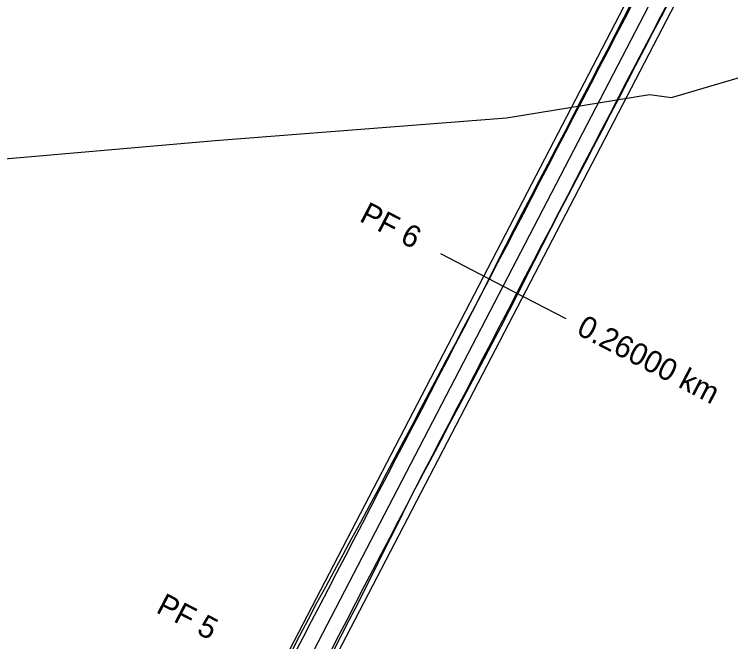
# Model space of a CAD drawing. Extents: x -555887 to -552101, y -1100251 to -1096546.
# Drawn here: x -553807.8 to -553726.6, y -1097465.4 to -1097394.3 of the extents above; entities that cross this region are included whole.
import ezdxf

# ---------------------------------------------------------------- set-up
doc = ezdxf.new("R2010")
doc.units = 0
for name, color, linetype in [('PARCELY_cesty', 7, 'Continuous'), ('POLYGONY_SITUACE_PF', 7, 'Continuous'), ('POLYGONY_SITUACE_PF_POPISY', 7, 'Continuous'), ('POLYGONY_SITUACE_PO', 7, 'Continuous'), ('vrstevnice', 7, 'Continuous')]:
    doc.layers.add(name, color=color, linetype=linetype)

msp = doc.modelspace()

# ---------------------------------------------------------------- linework, layer by layer
at = {"layer": 'PARCELY_cesty'}
for points in [[(-553665.731, -1097263.939), (-553869.18, -1097655.12), (-553873.9, -1097664.18), (-553876.67, -1097669.5)], [(-553672.865, -1097266.819), (-553859.38, -1097625.46)]]:
    msp.add_lwpolyline(points, dxfattribs=at)
at = {"layer": 'POLYGONY_SITUACE_PF'}
for p, q in [((-553759.461, -1097421.407), (-553752.363, -1097425.098)), ((-553752.363, -1097425.098), (-553745.266, -1097428.789))]:
    msp.add_line(p, q, dxfattribs=at)
at = {"layer": 'POLYGONY_SITUACE_PO'}
for p, q in [((-553872.328, -1097655.768), (-553671.456, -1097269.528)), ((-553734.469, -1097394.484), (-553733.508, -1097392.636)), ((-553734.469, -1097394.484), (-553733.508, -1097392.636)), ((-553734.417, -1097394.512), (-553733.459, -1097392.661)), ((-553737.709, -1097392.799), (-553738.667, -1097394.65)), ((-553738.536, -1097394.718), (-553737.575, -1097392.869)), ((-553738.536, -1097394.718), (-553737.575, -1097392.869)), ((-553738.667, -1097394.65), (-553739.624, -1097396.5)), ((-553739.497, -1097396.566), (-553738.536, -1097394.718)), ((-553739.497, -1097396.566), (-553738.536, -1097394.718)), ((-553735.431, -1097396.333), (-553734.469, -1097394.484)), ((-553735.431, -1097396.333), (-553734.469, -1097394.484)), ((-553735.374, -1097396.362), (-553734.417, -1097394.512)), ((-553739.624, -1097396.5), (-553740.581, -1097398.35)), ((-553740.458, -1097398.414), (-553739.497, -1097396.566)), ((-553740.458, -1097398.414), (-553739.497, -1097396.566)), ((-553736.392, -1097398.181), (-553735.431, -1097396.333)), ((-553736.392, -1097398.181), (-553735.431, -1097396.333)), ((-553736.333, -1097398.211), (-553735.374, -1097396.362)), ((-553740.581, -1097398.35), (-553741.539, -1097400.201)), ((-553741.42, -1097400.263), (-553740.458, -1097398.414)), ((-553741.42, -1097400.263), (-553740.458, -1097398.414)), ((-553737.353, -1097400.029), (-553736.392, -1097398.181)), ((-553737.353, -1097400.029), (-553736.392, -1097398.181)), ((-553737.296, -1097400.059), (-553736.333, -1097398.211)), ((-553738.314, -1097401.878), (-553737.353, -1097400.029)), ((-553738.314, -1097401.878), (-553737.353, -1097400.029)), ((-553738.258, -1097401.907), (-553737.296, -1097400.059)), ((-553741.539, -1097400.201), (-553742.496, -1097402.051)), ((-553742.381, -1097402.111), (-553741.42, -1097400.263)), ((-553742.381, -1097402.111), (-553741.42, -1097400.263)), ((-553742.496, -1097402.051), (-553743.457, -1097403.9)), ((-553743.342, -1097403.959), (-553742.381, -1097402.111)), ((-553743.342, -1097403.959), (-553742.381, -1097402.111)), ((-553739.276, -1097403.726), (-553738.314, -1097401.878)), ((-553739.276, -1097403.726), (-553738.314, -1097401.878)), ((-553739.22, -1097403.755), (-553738.258, -1097401.907)), ((-553743.457, -1097403.9), (-553744.419, -1097405.748)), ((-553744.303, -1097405.808), (-553743.342, -1097403.959)), ((-553744.303, -1097405.808), (-553743.342, -1097403.959)), ((-553740.237, -1097405.574), (-553739.276, -1097403.726)), ((-553740.237, -1097405.574), (-553739.276, -1097403.726)), ((-553740.182, -1097405.603), (-553739.22, -1097403.755)), ((-553744.419, -1097405.748), (-553745.381, -1097407.596)), ((-553741.198, -1097407.422), (-553740.237, -1097405.574)), ((-553741.198, -1097407.422), (-553740.237, -1097405.574)), ((-553741.144, -1097407.451), (-553740.182, -1097405.603)), ((-553745.265, -1097407.656), (-553744.303, -1097405.808)), ((-553745.265, -1097407.656), (-553744.303, -1097405.808)), ((-553745.381, -1097407.596), (-553746.343, -1097409.443)), ((-553746.226, -1097409.504), (-553745.265, -1097407.656)), ((-553746.226, -1097409.504), (-553745.265, -1097407.656)), ((-553742.159, -1097409.271), (-553741.198, -1097407.422)), ((-553742.159, -1097409.271), (-553741.198, -1097407.422)), ((-553742.106, -1097409.299), (-553741.144, -1097407.451)), ((-553746.343, -1097409.443), (-553747.305, -1097411.291)), ((-553747.187, -1097411.353), (-553746.226, -1097409.504)), ((-553747.187, -1097411.353), (-553746.226, -1097409.504)), ((-553743.121, -1097411.119), (-553742.159, -1097409.271)), ((-553743.121, -1097411.119), (-553742.159, -1097409.271)), ((-553743.068, -1097411.147), (-553742.106, -1097409.299)), ((-553747.305, -1097411.291), (-553748.267, -1097413.139)), ((-553748.148, -1097413.201), (-553747.187, -1097411.353)), ((-553748.148, -1097413.201), (-553747.187, -1097411.353)), ((-553744.082, -1097412.967), (-553743.121, -1097411.119)), ((-553744.082, -1097412.967), (-553743.121, -1097411.119)), ((-553744.03, -1097412.995), (-553743.068, -1097411.147)), ((-553745.043, -1097414.816), (-553744.082, -1097412.967)), ((-553745.043, -1097414.816), (-553744.082, -1097412.967)), ((-553744.992, -1097414.842), (-553744.03, -1097412.995)), ((-553748.267, -1097413.139), (-553749.229, -1097414.987)), ((-553749.11, -1097415.049), (-553748.148, -1097413.201)), ((-553749.11, -1097415.049), (-553748.148, -1097413.201)), ((-553749.229, -1097414.987), (-553750.191, -1097416.835)), ((-553750.071, -1097416.897), (-553749.11, -1097415.049)), ((-553750.071, -1097416.897), (-553749.11, -1097415.049)), ((-553746.004, -1097416.664), (-553745.043, -1097414.816)), ((-553746.004, -1097416.664), (-553745.043, -1097414.816)), ((-553745.954, -1097416.69), (-553744.992, -1097414.842)), ((-553750.191, -1097416.835), (-553751.149, -1097418.685)), ((-553751.032, -1097418.746), (-553750.071, -1097416.897)), ((-553751.032, -1097418.746), (-553750.071, -1097416.897)), ((-553746.966, -1097418.512), (-553746.004, -1097416.664)), ((-553746.966, -1097418.512), (-553746.004, -1097416.664)), ((-553746.916, -1097418.538), (-553745.954, -1097416.69)), ((-553751.149, -1097418.685), (-553752.09, -1097420.544)), ((-553751.993, -1097420.594), (-553751.032, -1097418.746)), ((-553751.993, -1097420.594), (-553751.032, -1097418.746)), ((-553747.927, -1097420.361), (-553746.966, -1097418.512)), ((-553747.927, -1097420.361), (-553746.966, -1097418.512)), ((-553747.873, -1097420.389), (-553746.916, -1097418.538)), ((-553748.888, -1097422.209), (-553747.927, -1097420.361)), ((-553748.888, -1097422.209), (-553747.927, -1097420.361)), ((-553748.814, -1097422.248), (-553747.873, -1097420.389)), ((-553752.09, -1097420.544), (-553753.031, -1097422.403)), ((-553752.955, -1097422.442), (-553751.993, -1097420.594)), ((-553752.955, -1097422.442), (-553751.993, -1097420.594)), ((-553753.031, -1097422.403), (-553753.972, -1097424.262)), ((-553753.916, -1097424.291), (-553752.955, -1097422.442)), ((-553753.916, -1097424.291), (-553752.955, -1097422.442)), ((-553749.849, -1097424.057), (-553748.888, -1097422.209)), ((-553749.849, -1097424.057), (-553748.888, -1097422.209)), ((-553749.755, -1097424.106), (-553748.814, -1097422.248)), ((-553753.972, -1097424.262), (-553754.913, -1097426.12)), ((-553754.877, -1097426.139), (-553753.916, -1097424.291)), ((-553754.877, -1097426.139), (-553753.916, -1097424.291)), ((-553750.811, -1097425.906), (-553749.849, -1097424.057)), ((-553750.811, -1097425.906), (-553749.849, -1097424.057)), ((-553750.696, -1097425.965), (-553749.755, -1097424.106)), ((-553751.772, -1097427.754), (-553750.811, -1097425.906)), ((-553751.772, -1097427.754), (-553750.811, -1097425.906)), ((-553751.637, -1097427.824), (-553750.696, -1097425.965)), ((-553754.913, -1097426.12), (-553755.868, -1097427.972)), ((-553755.838, -1097427.987), (-553754.877, -1097426.139)), ((-553755.838, -1097427.987), (-553754.877, -1097426.139)), ((-553755.868, -1097427.972), (-553756.846, -1097429.812)), ((-553756.8, -1097429.836), (-553755.838, -1097427.987)), ((-553756.8, -1097429.836), (-553755.838, -1097427.987)), ((-553752.733, -1097429.602), (-553751.772, -1097427.754)), ((-553752.733, -1097429.602), (-553751.772, -1097427.754)), ((-553752.596, -1097429.673), (-553751.637, -1097427.824)), ((-553756.846, -1097429.812), (-553757.825, -1097431.65)), ((-553757.761, -1097431.684), (-553756.8, -1097429.836)), ((-553757.761, -1097431.684), (-553756.8, -1097429.836)), ((-553753.694, -1097431.451), (-553752.733, -1097429.602)), ((-553753.694, -1097431.451), (-553752.733, -1097429.602)), ((-553753.564, -1097431.518), (-553752.596, -1097429.673)), ((-553757.825, -1097431.65), (-553758.811, -1097433.486)), ((-553758.722, -1097433.532), (-553757.761, -1097431.684)), ((-553758.722, -1097433.532), (-553757.761, -1097431.684)), ((-553754.656, -1097433.299), (-553753.694, -1097431.451)), ((-553754.656, -1097433.299), (-553753.694, -1097431.451)), ((-553754.532, -1097433.363), (-553753.564, -1097431.518)), ((-553755.617, -1097435.147), (-553754.656, -1097433.299)), ((-553755.617, -1097435.147), (-553754.656, -1097433.299)), ((-553755.5, -1097435.208), (-553754.532, -1097433.363)), ((-553758.811, -1097433.486), (-553759.785, -1097435.328)), ((-553759.683, -1097435.381), (-553758.722, -1097433.532)), ((-553759.683, -1097435.381), (-553758.722, -1097433.532)), ((-553759.785, -1097435.328), (-553760.757, -1097437.17)), ((-553760.645, -1097437.229), (-553759.683, -1097435.381)), ((-553760.645, -1097437.229), (-553759.683, -1097435.381)), ((-553756.578, -1097436.996), (-553755.617, -1097435.147)), ((-553756.578, -1097436.996), (-553755.617, -1097435.147)), ((-553756.477, -1097437.048), (-553755.5, -1097435.208)), ((-553760.757, -1097437.17), (-553761.73, -1097439.013)), ((-553761.606, -1097439.077), (-553760.645, -1097437.229)), ((-553761.606, -1097439.077), (-553760.645, -1097437.229)), ((-553757.539, -1097438.844), (-553756.578, -1097436.996)), ((-553757.539, -1097438.844), (-553756.578, -1097436.996)), ((-553757.456, -1097438.887), (-553756.477, -1097437.048)), ((-553761.73, -1097439.013), (-553762.702, -1097440.855)), ((-553762.567, -1097440.926), (-553761.606, -1097439.077)), ((-553762.567, -1097440.926), (-553761.606, -1097439.077)), ((-553758.501, -1097440.692), (-553757.539, -1097438.844)), ((-553758.501, -1097440.692), (-553757.539, -1097438.844)), ((-553758.434, -1097440.727), (-553757.456, -1097438.887)), ((-553759.462, -1097442.54), (-553758.501, -1097440.692)), ((-553759.462, -1097442.54), (-553758.501, -1097440.692)), ((-553759.413, -1097442.566), (-553758.434, -1097440.727)), ((-553762.702, -1097440.855), (-553763.674, -1097442.698)), ((-553763.528, -1097442.774), (-553762.567, -1097440.926)), ((-553763.528, -1097442.774), (-553762.567, -1097440.926)), ((-553763.674, -1097442.698), (-553764.647, -1097444.54)), ((-553764.49, -1097444.622), (-553763.528, -1097442.774)), ((-553764.49, -1097444.622), (-553763.528, -1097442.774)), ((-553760.423, -1097444.389), (-553759.462, -1097442.54)), ((-553760.423, -1097444.389), (-553759.462, -1097442.54)), ((-553760.391, -1097444.405), (-553759.413, -1097442.566)), ((-553764.647, -1097444.54), (-553765.619, -1097446.383)), ((-553765.451, -1097446.47), (-553764.49, -1097444.622)), ((-553765.451, -1097446.47), (-553764.49, -1097444.622)), ((-553761.385, -1097446.237), (-553760.423, -1097444.389)), ((-553761.385, -1097446.237), (-553760.423, -1097444.389)), ((-553761.37, -1097446.245), (-553760.391, -1097444.405)), ((-553765.619, -1097446.383), (-553766.592, -1097448.225)), ((-553762.346, -1097448.085), (-553761.385, -1097446.237)), ((-553762.346, -1097448.085), (-553761.385, -1097446.237)), ((-553762.174, -1097447.755), (-553761.37, -1097446.245)), ((-553766.412, -1097448.319), (-553765.451, -1097446.47)), ((-553766.412, -1097448.319), (-553765.451, -1097446.47)), ((-553762.343, -1097448.087), (-553762.174, -1097447.755)), ((-553766.592, -1097448.225), (-553767.573, -1097450.063)), ((-553767.373, -1097450.167), (-553766.412, -1097448.319)), ((-553767.373, -1097450.167), (-553766.412, -1097448.319)), ((-553763.307, -1097449.934), (-553762.346, -1097448.085)), ((-553763.307, -1097449.934), (-553762.346, -1097448.085)), ((-553763.275, -1097449.95), (-553762.343, -1097448.087)), ((-553767.573, -1097450.063), (-553768.565, -1097451.896)), ((-553768.335, -1097452.015), (-553767.373, -1097450.167)), ((-553768.335, -1097452.015), (-553767.373, -1097450.167)), ((-553764.268, -1097451.782), (-553763.307, -1097449.934)), ((-553764.268, -1097451.782), (-553763.307, -1097449.934)), ((-553764.207, -1097451.814), (-553763.275, -1097449.95)), ((-553768.565, -1097451.896), (-553769.558, -1097453.728)), ((-553769.296, -1097453.864), (-553768.335, -1097452.015)), ((-553769.296, -1097453.864), (-553768.335, -1097452.015)), ((-553765.23, -1097453.63), (-553764.268, -1097451.782)), ((-553765.23, -1097453.63), (-553764.268, -1097451.782)), ((-553765.14, -1097453.677), (-553764.207, -1097451.814)), ((-553769.558, -1097453.728), (-553770.55, -1097455.56)), ((-553766.191, -1097455.479), (-553765.23, -1097453.63)), ((-553766.191, -1097455.479), (-553765.23, -1097453.63)), ((-553766.072, -1097455.541), (-553765.14, -1097453.677)), ((-553770.257, -1097455.712), (-553769.296, -1097453.864)), ((-553770.257, -1097455.712), (-553769.296, -1097453.864)), ((-553770.55, -1097455.56), (-553771.543, -1097457.392)), ((-553771.218, -1097457.56), (-553770.257, -1097455.712)), ((-553771.218, -1097457.56), (-553770.257, -1097455.712)), ((-553767.152, -1097457.327), (-553766.191, -1097455.479)), ((-553767.152, -1097457.327), (-553766.191, -1097455.479)), ((-553767.004, -1097457.404), (-553766.072, -1097455.541)), ((-553771.543, -1097457.392), (-553772.536, -1097459.224)), ((-553772.18, -1097459.409), (-553771.218, -1097457.56)), ((-553772.18, -1097459.409), (-553771.218, -1097457.56)), ((-553768.113, -1097459.175), (-553767.152, -1097457.327)), ((-553768.113, -1097459.175), (-553767.152, -1097457.327)), ((-553767.936, -1097459.268), (-553767.004, -1097457.404)), ((-553772.536, -1097459.224), (-553773.526, -1097461.057)), ((-553773.141, -1097461.257), (-553772.18, -1097459.409)), ((-553773.141, -1097461.257), (-553772.18, -1097459.409)), ((-553769.075, -1097461.024), (-553768.113, -1097459.175)), ((-553769.075, -1097461.024), (-553768.113, -1097459.175)), ((-553768.865, -1097461.133), (-553767.936, -1097459.268)), ((-553770.036, -1097462.872), (-553769.075, -1097461.024)), ((-553770.036, -1097462.872), (-553769.075, -1097461.024)), ((-553773.526, -1097461.057), (-553774.494, -1097462.902)), ((-553774.102, -1097463.105), (-553773.141, -1097461.257)), ((-553774.102, -1097463.105), (-553773.141, -1097461.257)), ((-553769.82, -1097462.984), (-553768.865, -1097461.133)), ((-553774.494, -1097462.902), (-553775.461, -1097464.747)), ((-553775.063, -1097464.954), (-553774.102, -1097463.105)), ((-553775.063, -1097464.954), (-553774.102, -1097463.105)), ((-553770.997, -1097464.72), (-553770.036, -1097462.872)), ((-553770.997, -1097464.72), (-553770.036, -1097462.872)), ((-553770.776, -1097464.835), (-553769.82, -1097462.984)), ((-553775.461, -1097464.747), (-553776.428, -1097466.592)), ((-553776.025, -1097466.802), (-553775.063, -1097464.954)), ((-553776.025, -1097466.802), (-553775.063, -1097464.954)), ((-553771.958, -1097466.569), (-553770.997, -1097464.72)), ((-553771.958, -1097466.569), (-553770.997, -1097464.72)), ((-553771.731, -1097466.687), (-553770.776, -1097464.835))]:
    msp.add_line(p, q, dxfattribs=at)
at = {"layer": 'vrstevnice'}
msp.add_lwpolyline([(-553820.669, -1097411.697), (-553785.048, -1097408.589), (-553751.981, -1097406.024), (-553735.77, -1097403.356), (-553733.277, -1097403.712), (-553708.618, -1097396.44), (-553685.955, -1097384.829)], dxfattribs=at)

# ---------------------------------------------------------------- texts
at = {"layer": 'POLYGONY_SITUACE_PF_POPISY'}
for s, p in [('PF 6', (-553768.794, -1097417.68)), ('0.26000 km', (-553744.172, -1097430.485)), ('PF 5', (-553791.864, -1097462.04))]:
    msp.add_text(s, height=2.5, rotation=332.52237, dxfattribs=at).set_placement(p)

doc.saveas('drawing.dxf')
